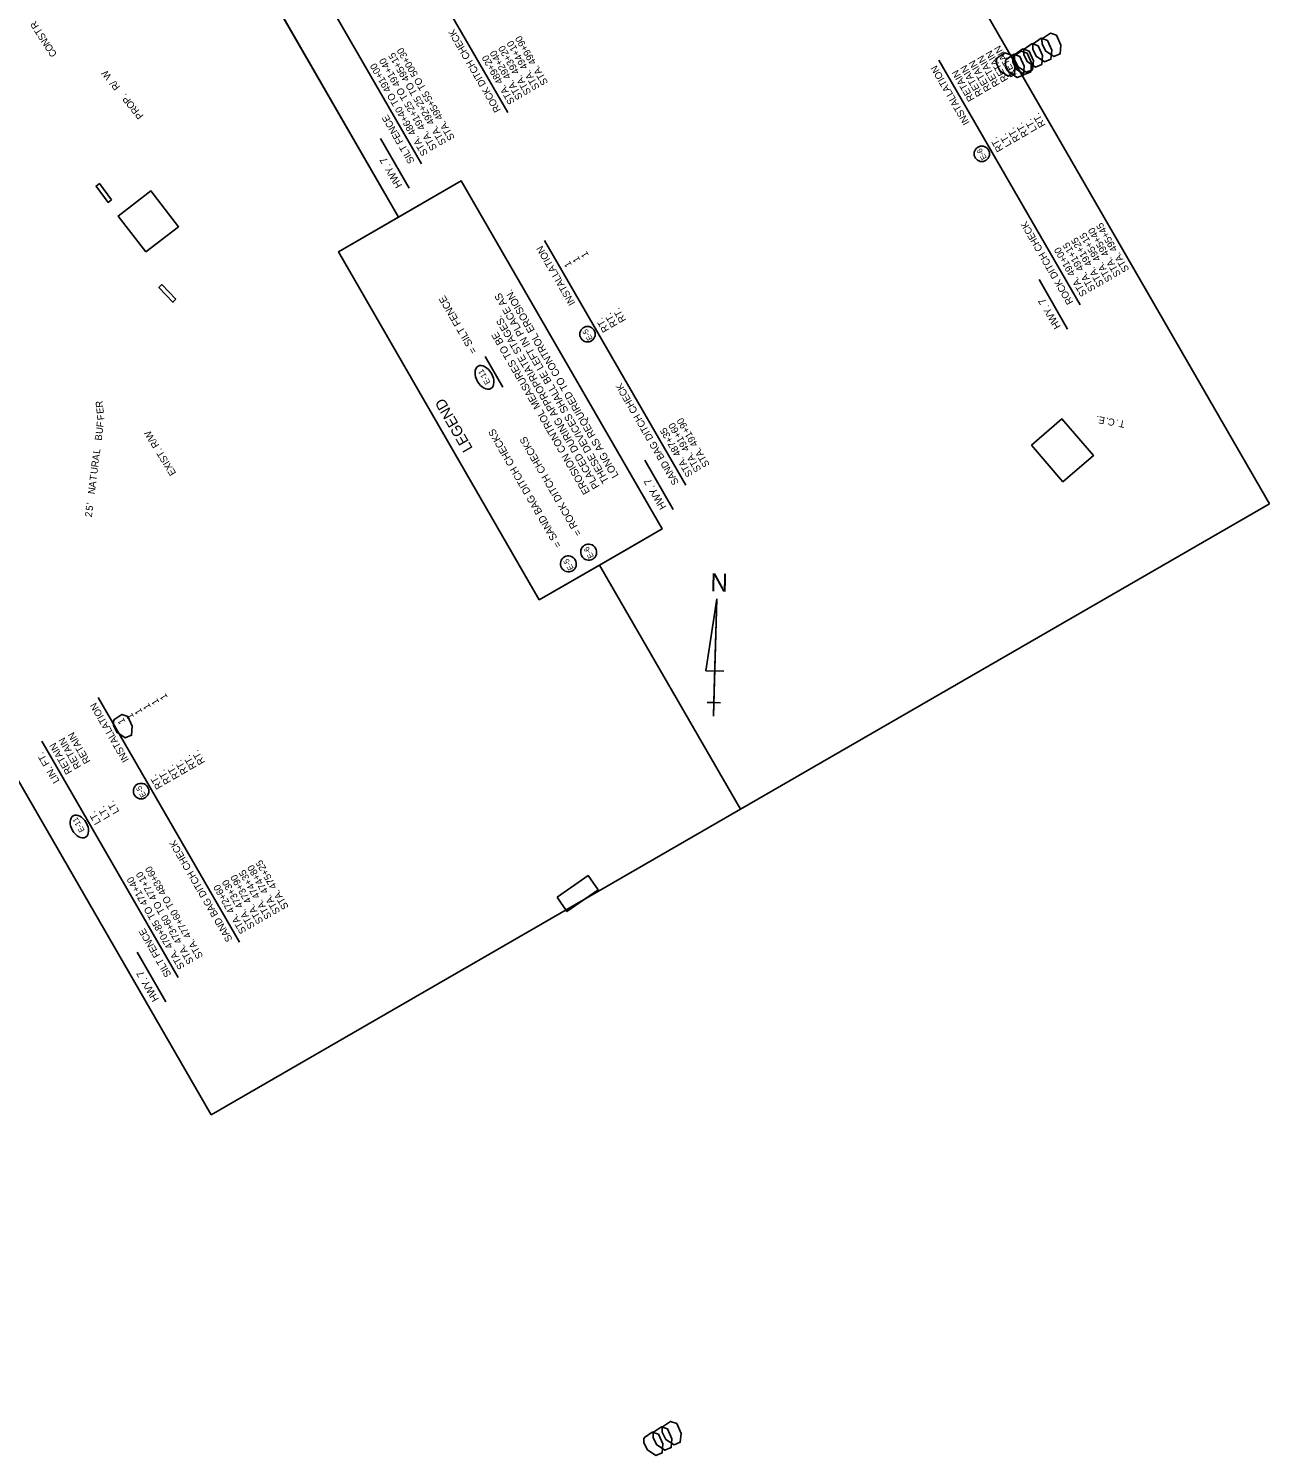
# Model space of a CAD drawing. Extents: x 956270 to 957915, y 1920230 to 1922423.
# Drawn here: x 956857 to 957915, y 1920230 to 1921447 of the extents above; entities that cross this region are included whole.
import ezdxf

# ---------------------------------------------------------------- set-up
doc = ezdxf.new("R2010")
doc.units = 0
for name, color, linetype in [('1', 7, 'Continuous'), ('44', 7, 'Continuous'), ('63', 7, 'Continuous'), ('Level 1', 7, 'Continuous'), ('Level 44', 7, 'Continuous'), ('NO PLOT', 7, 'Continuous'), ('R_Draft', 7, 'Continuous'), ('S_TREE', 7, 'Continuous')]:
    doc.layers.add(name, color=color, linetype=linetype)

msp = doc.modelspace()

# ---------------------------------------------------------------- linework, layer by layer
at = {"layer": '1'}
for p, q in [((957172.3, 1921286.1), (957029.2, 1921533.9)), ((957225.7, 1921317), (957120.9, 1921256.4)), ((957292.2, 1920959.7), (957120.9, 1921256.4)), ((957367.7, 1921003.2), (957292.2, 1920959.7)), ((957463.8, 1920781), (957343.6, 1920989.3))]:
    msp.add_line(p, q, dxfattribs=at)
msp.add_lwpolyline([(957367.7, 1921003.2), (957397.1, 1921020.2), (957225.7, 1921317)], dxfattribs=at)
for centre in [(957669.8, 1921340.1), (957333.4, 1921186.2), (956952.6, 1920796.5)]:
    msp.add_circle(centre, 6.61, dxfattribs=at)
msp.add_ellipse((956899.9, 1920766.3), major_axis=(-5.26, 9.11), ratio=0.638788, dxfattribs=at)
at = {"layer": '44'}
for p, q in [((957265.4, 1921375.2), (957144.9, 1921583.9)), ((957191.8, 1921331.6), (957075.4, 1921533.2)), ((957753.6, 1921211.3), (957633.1, 1921420)), ((957181.2, 1921310.8), (957156.7, 1921353.1)), ((957417.3, 1921057.4), (957296.8, 1921266.1)), ((957743, 1921190.5), (957718.6, 1921232.8)), ((957406.6, 1921036.6), (957382.2, 1921078.9)), ((957036.4, 1920667.7), (956915.9, 1920876.4)), ((956984.3, 1920637.6), (956867.9, 1920839.2)), ((956973.7, 1920616.8), (956949.2, 1920659.1))]:
    msp.add_line(p, q, dxfattribs=at)
at = {"layer": '63'}
for p, q in [((957443.6, 1920960.4), (957434.3, 1920899.1)), ((957440.9, 1920860.4), (957443.6, 1920960.4)), ((957443.6, 1920960.4), (957441.5, 1920883.5)), ((957434.3, 1920899.1), (957449.6, 1920898.7)), ((957440.9, 1920860.4), (957441.5, 1920883.5)), ((957441.2, 1920872), (957435.5, 1920872.1)), ((957435.5, 1920872.1), (957447, 1920871.8)), ((957440.9, 1920860.4), (957441.2, 1920872))]:
    msp.add_line(p, q, dxfattribs=at)
at = {"layer": 'Level 1'}
for centre, major_axis, ratio in [((957245.5, 1921149.4), (-5.48, 9.49), 0.622952), ((957334.4, 1921000.3), (3.44, -5.96), 0.97521), ((957317.1, 1920990.3), (3.44, -5.96), 0.97521)]:
    msp.add_ellipse(centre, major_axis=major_axis, ratio=ratio, dxfattribs=at)
at = {"layer": 'Level 44'}
msp.add_lwpolyline([(957261.1, 1921141), (957246, 1921167.1)], dxfattribs=at)
at = {"layer": 'NO PLOT'}
for points in [[(957915.2, 1921041.6), (957117.5, 1922423.2), (956666.2, 1922162.6), (956816.7, 1921902), (956875.1, 1921935.7), (957087.6, 1921567.7), (957029.2, 1921533.9), (957172.3, 1921286.1), (957225.7, 1921317), (957397.1, 1921020.2), (957343.6, 1920989.3), (957463.8, 1920781)], [(957915.2, 1921041.6), (957117.5, 1922423.2), (956666.2, 1922162.6), (956816.7, 1921902), (956875.1, 1921935.7), (957087.6, 1921567.7), (957029.2, 1921533.9), (957172.3, 1921286.1), (957225.7, 1921317), (957397.1, 1921020.2), (957343.6, 1920989.3), (957463.8, 1920781)], [(957915.2, 1921041.6), (957117.5, 1922423.2), (956666.2, 1922162.6), (956816.7, 1921902), (956875.1, 1921935.7), (957087.6, 1921567.7), (957029.2, 1921533.9), (957172.3, 1921286.1), (957225.7, 1921317), (957397.1, 1921020.2), (957343.6, 1920989.3), (957463.8, 1920781)], [(957915.2, 1921041.6), (957117.5, 1922423.2), (956666.2, 1922162.6), (956816.7, 1921902), (956875.1, 1921935.7), (957087.6, 1921567.7), (957029.2, 1921533.9), (957172.3, 1921286.1), (957225.7, 1921317), (957397.1, 1921020.2), (957343.6, 1920989.3), (957463.8, 1920781)], [(957915.2, 1921041.6), (957117.5, 1922423.2), (956666.2, 1922162.6), (956816.7, 1921902), (956875.1, 1921935.7), (957087.6, 1921567.7), (957029.2, 1921533.9), (957172.3, 1921286.1), (957225.7, 1921317), (957397.1, 1921020.2), (957343.6, 1920989.3), (957463.8, 1920781)], [(957012.5, 1920520.4), (956420.5, 1921545.9), (956463.3, 1921570.6), (956365.4, 1921740.1), (956378, 1921747.4), (956270.3, 1921934.1), (956666.2, 1922162.6), (956816.7, 1921902), (956750, 1921863.5), (956962.5, 1921495.4), (957029.2, 1921533.9), (957172.3, 1921286.1), (957120.9, 1921256.4), (957292.2, 1920959.7), (957343.6, 1920989.3), (957463.8, 1920781)], [(957012.5, 1920520.4), (956420.5, 1921545.9), (956463.3, 1921570.6), (956365.4, 1921740.1), (956378, 1921747.4), (956270.3, 1921934.1), (956666.2, 1922162.6), (956816.7, 1921902), (956750, 1921863.5), (956962.5, 1921495.4), (957029.2, 1921533.9), (957172.3, 1921286.1), (957120.9, 1921256.4), (957292.2, 1920959.7), (957343.6, 1920989.3), (957463.8, 1920781)], [(957012.5, 1920520.4), (956420.5, 1921545.9), (956463.3, 1921570.6), (956365.4, 1921740.1), (956378, 1921747.4), (956270.3, 1921934.1), (956666.2, 1922162.6), (956816.7, 1921902), (956750, 1921863.5), (956962.5, 1921495.4), (957029.2, 1921533.9), (957172.3, 1921286.1), (957120.9, 1921256.4), (957292.2, 1920959.7), (957343.6, 1920989.3), (957463.8, 1920781)], [(957012.5, 1920520.4), (956420.5, 1921545.9), (956463.3, 1921570.6), (956365.4, 1921740.1), (956378, 1921747.4), (956270.3, 1921934.1), (956666.2, 1922162.6), (956816.7, 1921902), (956750, 1921863.5), (956962.5, 1921495.4), (957029.2, 1921533.9), (957172.3, 1921286.1), (957120.9, 1921256.4), (957292.2, 1920959.7), (957343.6, 1920989.3), (957463.8, 1920781)], [(957012.5, 1920520.4), (956420.5, 1921545.9), (956463.3, 1921570.6), (956365.4, 1921740.1), (956378, 1921747.4), (956270.3, 1921934.1), (956666.2, 1922162.6), (956816.7, 1921902), (956750, 1921863.5), (956962.5, 1921495.4), (957029.2, 1921533.9), (957172.3, 1921286.1), (957120.9, 1921256.4), (957292.2, 1920959.7), (957343.6, 1920989.3), (957463.8, 1920781)], [(956927.3, 1921300.8), (956917, 1921314.7), (956914.2, 1921312.6), (956924.5, 1921298.7)], [(956956.7, 1921256.4), (956984.6, 1921277.9), (956961, 1921308.5), (956933.1, 1921287)], [(956982.3, 1921216), (956970.3, 1921228.6), (956967.8, 1921226.2), (956979.7, 1921213.5)], [(957712.1, 1921091.6), (957739, 1921060.3), (957765, 1921082.7), (957738.1, 1921114)], [(957307.5, 1920705.9), (957334.1, 1920724.4), (957342.5, 1920712.2), (957315.9, 1920693.7)]]:
    msp.add_lwpolyline(points, close=True, dxfattribs=at)
at = {"layer": 'S_TREE'}
for points in [[(957713.7, 1921433.9), (957720.5, 1921438.6), (957725.7, 1921436.7), (957729.4, 1921428.4), (957728.7, 1921420.8), (957723.3, 1921418.6), (957716.3, 1921423.3), (957713.4, 1921429.3), (957713.3, 1921433), (957714.3, 1921434.5)], [(957713.7, 1921433.9), (957720.5, 1921438.6), (957725.7, 1921436.7), (957729.4, 1921428.4), (957728.7, 1921420.8), (957723.3, 1921418.6), (957716.3, 1921423.3), (957713.4, 1921429.3), (957713.3, 1921433), (957714.3, 1921434.5)], [(957713.7, 1921433.9), (957720.5, 1921438.6), (957725.7, 1921436.7), (957729.4, 1921428.4), (957728.7, 1921420.8), (957723.3, 1921418.6), (957716.3, 1921423.3), (957713.4, 1921429.3), (957713.3, 1921433), (957714.3, 1921434.5)], [(957713.7, 1921433.9), (957720.5, 1921438.6), (957725.7, 1921436.7), (957729.4, 1921428.4), (957728.7, 1921420.8), (957723.3, 1921418.6), (957716.3, 1921423.3), (957713.4, 1921429.3), (957713.3, 1921433), (957714.3, 1921434.5)], [(957713.7, 1921433.9), (957720.5, 1921438.6), (957725.7, 1921436.7), (957729.4, 1921428.4), (957728.7, 1921420.8), (957723.3, 1921418.6), (957716.3, 1921423.3), (957713.4, 1921429.3), (957713.3, 1921433), (957714.3, 1921434.5)], [(957713.7, 1921433.9), (957720.5, 1921438.6), (957725.7, 1921436.7), (957729.4, 1921428.4), (957728.7, 1921420.8), (957723.3, 1921418.6), (957716.3, 1921423.3), (957713.4, 1921429.3), (957713.3, 1921433), (957714.3, 1921434.5)], [(957721.5, 1921438.4), (957728.3, 1921443.1), (957733.5, 1921441.2), (957737.1, 1921432.9), (957736.5, 1921425.3), (957731.1, 1921423.1), (957724.1, 1921427.8), (957721.2, 1921433.8), (957721.1, 1921437.5), (957722.1, 1921439)], [(957721.5, 1921438.4), (957728.3, 1921443.1), (957733.5, 1921441.2), (957737.1, 1921432.9), (957736.5, 1921425.3), (957731.1, 1921423.1), (957724.1, 1921427.8), (957721.2, 1921433.8), (957721.1, 1921437.5), (957722.1, 1921439)], [(957721.5, 1921438.4), (957728.3, 1921443.1), (957733.5, 1921441.2), (957737.1, 1921432.9), (957736.5, 1921425.3), (957731.1, 1921423.1), (957724.1, 1921427.8), (957721.2, 1921433.8), (957721.1, 1921437.5), (957722.1, 1921439)], [(957682.7, 1921421.6), (957689.4, 1921426.3), (957694.6, 1921424.5), (957698.3, 1921416.2), (957697.7, 1921408.5), (957692.3, 1921406.3), (957685.3, 1921411), (957682.3, 1921417.1), (957682.3, 1921420.8), (957683.2, 1921422.2)], [(957682.7, 1921421.6), (957689.4, 1921426.3), (957694.6, 1921424.5), (957698.3, 1921416.2), (957697.7, 1921408.5), (957692.3, 1921406.3), (957685.3, 1921411), (957682.3, 1921417.1), (957682.3, 1921420.8), (957683.2, 1921422.2)], [(957696.6, 1921423), (957703.4, 1921427.7), (957708.6, 1921425.9), (957712.3, 1921417.6), (957711.6, 1921410), (957706.2, 1921407.7), (957699.2, 1921412.4), (957696.3, 1921418.5), (957696.3, 1921422.2), (957697.2, 1921423.6)], [(957698.1, 1921424.9), (957704.9, 1921429.6), (957710.1, 1921427.7), (957713.8, 1921419.4), (957713.1, 1921411.8), (957707.7, 1921409.6), (957700.7, 1921414.3), (957697.8, 1921420.3), (957697.8, 1921424), (957698.7, 1921425.5)], [(957698.1, 1921424.9), (957704.9, 1921429.6), (957710.1, 1921427.7), (957713.8, 1921419.4), (957713.1, 1921411.8), (957707.7, 1921409.6), (957700.7, 1921414.3), (957697.8, 1921420.3), (957697.8, 1921424), (957698.7, 1921425.5)], [(957698.1, 1921424.9), (957704.9, 1921429.6), (957710.1, 1921427.7), (957713.8, 1921419.4), (957713.1, 1921411.8), (957707.7, 1921409.6), (957700.7, 1921414.3), (957697.8, 1921420.3), (957697.8, 1921424), (957698.7, 1921425.5)], [(957698.1, 1921424.9), (957704.9, 1921429.6), (957710.1, 1921427.7), (957713.8, 1921419.4), (957713.1, 1921411.8), (957707.7, 1921409.6), (957700.7, 1921414.3), (957697.8, 1921420.3), (957697.8, 1921424), (957698.7, 1921425.5)], [(957698.1, 1921424.9), (957704.9, 1921429.6), (957710.1, 1921427.7), (957713.8, 1921419.4), (957713.1, 1921411.8), (957707.7, 1921409.6), (957700.7, 1921414.3), (957697.8, 1921420.3), (957697.8, 1921424), (957698.7, 1921425.5)], [(957705.9, 1921429.4), (957712.7, 1921434.1), (957717.9, 1921432.2), (957721.6, 1921423.9), (957720.9, 1921416.3), (957715.5, 1921414.1), (957708.5, 1921418.8), (957705.6, 1921424.8), (957705.6, 1921428.5), (957706.5, 1921430)], [(957705.9, 1921429.4), (957712.7, 1921434.1), (957717.9, 1921432.2), (957721.6, 1921423.9), (957720.9, 1921416.3), (957715.5, 1921414.1), (957708.5, 1921418.8), (957705.6, 1921424.8), (957705.6, 1921428.5), (957706.5, 1921430)], [(957705.9, 1921429.4), (957712.7, 1921434.1), (957717.9, 1921432.2), (957721.6, 1921423.9), (957720.9, 1921416.3), (957715.5, 1921414.1), (957708.5, 1921418.8), (957705.6, 1921424.8), (957705.6, 1921428.5), (957706.5, 1921430)], [(957705.9, 1921429.4), (957712.7, 1921434.1), (957717.9, 1921432.2), (957721.6, 1921423.9), (957720.9, 1921416.3), (957715.5, 1921414.1), (957708.5, 1921418.8), (957705.6, 1921424.8), (957705.6, 1921428.5), (957706.5, 1921430)], [(957690.3, 1921420.4), (957697.1, 1921425.1), (957702.3, 1921423.2), (957706, 1921414.9), (957705.3, 1921407.3), (957700, 1921405.1), (957692.9, 1921409.8), (957690, 1921415.8), (957690, 1921419.5), (957690.9, 1921421)], [(957690.3, 1921420.4), (957697.1, 1921425.1), (957702.3, 1921423.2), (957706, 1921414.9), (957705.3, 1921407.3), (957700, 1921405.1), (957692.9, 1921409.8), (957690, 1921415.8), (957690, 1921419.5), (957690.9, 1921421)], [(957690.3, 1921420.4), (957697.1, 1921425.1), (957702.3, 1921423.2), (957706, 1921414.9), (957705.3, 1921407.3), (957700, 1921405.1), (957692.9, 1921409.8), (957690, 1921415.8), (957690, 1921419.5), (957690.9, 1921421)], [(956929.4, 1920857.2), (956936.2, 1920861.9), (956941.4, 1920860.1), (956945.1, 1920851.8), (956944.5, 1920844.2), (956939.1, 1920841.9), (956932, 1920846.7), (956929.1, 1920852.7), (956929.1, 1920856.4), (956930, 1920857.8)], [(957397.5, 1920254.1), (957404.3, 1920258.8), (957409.5, 1920257), (957413.2, 1920248.6), (957412.6, 1920241), (957407.2, 1920238.8), (957400.2, 1920243.5), (957397.2, 1920249.6), (957397.2, 1920253.3), (957398.1, 1920254.7)], [(957397.5, 1920254.1), (957404.3, 1920258.8), (957409.5, 1920257), (957413.2, 1920248.6), (957412.6, 1920241), (957407.2, 1920238.8), (957400.2, 1920243.5), (957397.2, 1920249.6), (957397.2, 1920253.3), (957398.1, 1920254.7)], [(957397.5, 1920254.1), (957404.3, 1920258.8), (957409.5, 1920257), (957413.2, 1920248.6), (957412.6, 1920241), (957407.2, 1920238.8), (957400.2, 1920243.5), (957397.2, 1920249.6), (957397.2, 1920253.3), (957398.1, 1920254.7)], [(957397.5, 1920254.1), (957404.3, 1920258.8), (957409.5, 1920257), (957413.2, 1920248.6), (957412.6, 1920241), (957407.2, 1920238.8), (957400.2, 1920243.5), (957397.2, 1920249.6), (957397.2, 1920253.3), (957398.1, 1920254.7)], [(957397.5, 1920254.1), (957404.3, 1920258.8), (957409.5, 1920257), (957413.2, 1920248.6), (957412.6, 1920241), (957407.2, 1920238.8), (957400.2, 1920243.5), (957397.2, 1920249.6), (957397.2, 1920253.3), (957398.1, 1920254.7)], [(957382, 1920245.1), (957388.7, 1920249.8), (957393.9, 1920248), (957397.6, 1920239.6), (957397, 1920232), (957391.6, 1920229.8), (957384.6, 1920234.5), (957381.6, 1920240.6), (957381.6, 1920244.3), (957382.5, 1920245.7)], [(957382, 1920245.1), (957388.7, 1920249.8), (957393.9, 1920248), (957397.6, 1920239.6), (957397, 1920232), (957391.6, 1920229.8), (957384.6, 1920234.5), (957381.6, 1920240.6), (957381.6, 1920244.3), (957382.5, 1920245.7)], [(957389.8, 1920249.6), (957396.5, 1920254.3), (957401.7, 1920252.5), (957405.4, 1920244.1), (957404.8, 1920236.5), (957399.4, 1920234.3), (957392.4, 1920239), (957389.4, 1920245.1), (957389.4, 1920248.8), (957390.3, 1920250.2)], [(957389.8, 1920249.6), (957396.5, 1920254.3), (957401.7, 1920252.5), (957405.4, 1920244.1), (957404.8, 1920236.5), (957399.4, 1920234.3), (957392.4, 1920239), (957389.4, 1920245.1), (957389.4, 1920248.8), (957390.3, 1920250.2)], [(957389.8, 1920249.6), (957396.5, 1920254.3), (957401.7, 1920252.5), (957405.4, 1920244.1), (957404.8, 1920236.5), (957399.4, 1920234.3), (957392.4, 1920239), (957389.4, 1920245.1), (957389.4, 1920248.8), (957390.3, 1920250.2)]]:
    msp.add_lwpolyline(points, dxfattribs=at)

# ---------------------------------------------------------------- texts
at = {"layer": '1'}
for s, p in [('E-6 ', (957674.2, 1921336.7)), ('E-5 ', (957338, 1921182.5)), ('E-5 ', (956957.1, 1920792.8)), ('E-11', (956904.6, 1920763))]:
    msp.add_text(s, height=4.8, rotation=120, dxfattribs=at).set_placement(p)
at = {"layer": '44'}
for s, height, p in [('ROCK DITCH CHECK', 6, (957259.7, 1921377.5)), ('STA. 499+90', 6, (957300, 1921400.7)), ('STA. 492+25 TO 495+15', 6, (957213.2, 1921349.4)), ('STA. 495+55 TO 500+30', 6, (957220.4, 1921353.6)), ('STA. 492+40', 6, (957278.4, 1921388.3)), ('STA. 493+20', 6, (957285.6, 1921392.4)), ('STA. 494+10', 6, (957292.8, 1921396.6)), ('RETAIN', 6, (957692.6, 1921403.5)), ('RETAIN', 6, (957699.8, 1921407.6)), ('STA. 486+40 TO 491+00', 6, (957197.5, 1921340.4)), ('STA. 491+25 TO 491+40', 6, (957205.3, 1921344.9)), ('STA. 489+20', 6, (957271.6, 1921384.3)), ('INSTALLATION', 6, (957659.6, 1921366.7)), ('RETAIN', 6, (957671, 1921391)), ('RETAIN', 6, (957678.2, 1921395.2)), ('RETAIN', 6, (957685.4, 1921399.3)), ('RETAIN', 6, (957663.8, 1921386.8)), ('SILT FENCE      ', 6, (957186.1, 1921333.8)), ('RT.', 6, (957710.1, 1921356.3)), ('LT.', 6, (957717.2, 1921360.6)), ('RT.', 6, (957724.4, 1921364.6)), ('RT.', 6, (957688.4, 1921343.8)), ('LT.', 6, (957695.6, 1921348.1)), ('RT.', 6, (957702.9, 1921352.1)), ('HWY. 7', 6.25, (957175.5, 1921313.1)), ('ROCK DITCH CHECK', 6, (957748, 1921213.6)), ('STA. 495+45', 6, (957795.8, 1921241.2)), ('STA. 491+25', 6, (957774.3, 1921228.7)), ('STA. 495+15', 6, (957781.5, 1921232.9)), ('STA. 495+40', 6, (957788.7, 1921237.1)), ('INSTALLATION', 6, (957323.2, 1921212.8)), ('1', 6, (957334.7, 1921253.6)), ('STA. 491+00', 6, (957759.8, 1921220.4)), ('STA. 491+15', 6, (957767.1, 1921224.6)), ('1', 6, (957320.3, 1921245.3)), ('1', 6, (957327.5, 1921249.4)), ('RT.', 6, (957366.5, 1921198.2)), ('HWY. 7', 6.25, (957737.3, 1921192.8)), ('RT.', 6, (957352.1, 1921189.9)), ('RT.', 6, (957359.3, 1921194.1)), ('SAND BAG DITCH CHECK', 6, (957411.6, 1921059.7)), ('STA. 491+60', 6, (957430.7, 1921070.7)), ('STA. 491+90', 6, (957437.9, 1921074.8)), ('STA. 487+35', 6, (957423.5, 1921066.5)), ('HWY. 7', 6.25, (957400.9, 1921038.9)), ('1', 6, (956975.5, 1920876.4)), ('INSTALLATION', 6, (956942.4, 1920823.1)), ('1', 6, (956953.9, 1920863.9)), ('1', 6, (956961.1, 1920868.1)), ('1', 6, (956968.3, 1920872.2)), ('1', 6, (956939.4, 1920855.6)), ('1', 6, (956946.7, 1920859.7)), ('RETAIN', 6, (956901.7, 1920817.4)), ('RETAIN', 6, (956909.6, 1920821.9)), ('LIN. FT.', 6, (956883.2, 1920805.2)), ('RETAIN', 6, (956894, 1920812.9)), ('RT.', 6, (957007.3, 1920821)), ('RT.', 6, (956985.7, 1920808.5)), ('RT.', 6, (956992.9, 1920812.7)), ('RT.', 6, (957000.1, 1920816.9)), ('RT.', 6, (956971.2, 1920800.2)), ('RT.', 6, (956978.4, 1920804.4)), ('LT.', 6, (956926.3, 1920774.4)), ('LT.', 6, (956934.2, 1920779)), ('LT.', 6, (956918.6, 1920770)), ('SAND BAG DITCH CHECK', 6, (957030.8, 1920670)), ('STA. 477+60 TO 483+60', 6, (957005.7, 1920655.5)), ('STA. 474+80', 6, (957071.5, 1920693.5)), ('STA. 475+25', 6, (957078.7, 1920697.6)), ('STA. 470+85 TO 471+40', 6, (956990, 1920646.5)), ('STA. 473+60 TO 477+10', 6, (956997.8, 1920650.9)), ('STA. 473+30', 6, (957049.9, 1920681)), ('STA. 473+90', 6, (957057.1, 1920685.2)), ('STA. 474+35', 6, (957064.3, 1920689.3)), ('STA. 472+60', 6, (957042.6, 1920676.8)), ('SILT FENCE      ', 6, (956978.6, 1920639.9)), ('HWY. 7', 6.25, (956968, 1920619.1))]:
    msp.add_text(s, height=height, rotation=120, dxfattribs=at).set_placement(p)
at = {"layer": '63'}
msp.add_text('N', height=15.4, rotation=358.5016, dxfattribs=at).set_placement((957438.1, 1920967))
at = {"layer": 'Level 1'}
for s, height, p in [('= SILT FENCE', 6.25, (957239.3, 1921171.7)), ('THESE DEVICES SHALL BE LEFT IN PLACE AS ', 6.25, (957352, 1921061.1)), ('LONG AS REQUIRED TO CONTROL EROSION.', 6.25, (957360.2, 1921065.8)), ('PLACED DURING APPROPRIATE STAGES. ', 6.25, (957343.9, 1921056.4)), ('EROSION CONTROL MEASURES TO BE', 6.25, (957335.7, 1921051.7)), ('E-11 ', 4.88, (957250.8, 1921145)), ('= SAND BAG DITCH CHECKS', 6.25, (957311.5, 1921006.2)), ('= ROCK DITCH CHECKS', 6.25, (957328.8, 1921016.2)), ('E-6 ', 4.88, (957339, 1920996.7)), ('E-5 ', 4.88, (957321.8, 1920986.5))]:
    msp.add_text(s, height=height, rotation=120, dxfattribs=at).set_placement(p)
at = {"layer": 'Level 44'}
msp.add_text('LEGEND', height=9.14, rotation=120, dxfattribs=at).set_placement((957235.8, 1921088.9))
at = {"layer": 'R_Draft'}
for s, rotation, p in [('R', 122.5222, (956865.7, 1921449)), ('T', 122.5222, (956868.9, 1921444)), ('S', 122.9434, (956871.9, 1921439.3)), ('N', 122.9434, (956875, 1921434.5)), ('O', 122.9562, (956878.2, 1921429.6)), ('C', 126.5389, (956881.2, 1921425.3)), ('W', 129.1474, (956927.7, 1921406.2)), ('/', 129.1474, (956931.4, 1921401.7)), ('R', 129.1474, (956935, 1921397.3)), ('.', 129.1474, (956940.6, 1921390.4)), ('P', 129.1474, (956944.2, 1921386)), ('O', 129.1474, (956947.9, 1921381.4)), ('R', 129.1474, (956951.4, 1921377)), ('P', 129.1474, (956955, 1921372.6)), ('R', 95.8222, (956920.2, 1921123.9)), ('E', 95.8222, (956920.8, 1921118.6)), ('F', 82.6936, (956920.3, 1921106.5)), ('F', 95.8222, (956921.3, 1921113.2)), ('.', 169.8911, (957769.9, 1921116.2)), ('E', 169.8911, (957775.2, 1921115.3)), ('.', 169.8911, (957778.1, 1921114.7)), ('C', 169.8911, (957783.7, 1921113.7)), ('.', 169.8911, (957786.6, 1921113.2)), ('T', 169.8911, (957792.3, 1921112.2)), ('B', 82.6936, (956918.9, 1921095.2)), ('U', 82.6936, (956919.6, 1921100.8)), ('EXIST. R/W', 121.503, (956982.7, 1921067.8)), ('L', 82.6936, (956917.4, 1921083.9)), ('U', 82.6936, (956915.2, 1921066.7)), ('R', 82.6936, (956915.9, 1921072.4)), ('A', 82.6936, (956916.7, 1921078.1)), ('A', 82.6936, (956913.7, 1921055.1)), ('T', 82.6936, (956914.5, 1921060.9)), ('N', 82.6936, (956913, 1921049.5)), ('5', 82.6936, (956911.2, 1921035.3)), ("'", 82.6936, (956911.9, 1921040.6)), ('2', 82.6936, (956910.5, 1921029.9))]:
    msp.add_text(s, height=6, rotation=rotation, dxfattribs=at).set_placement(p)

doc.saveas('drawing.dxf')
